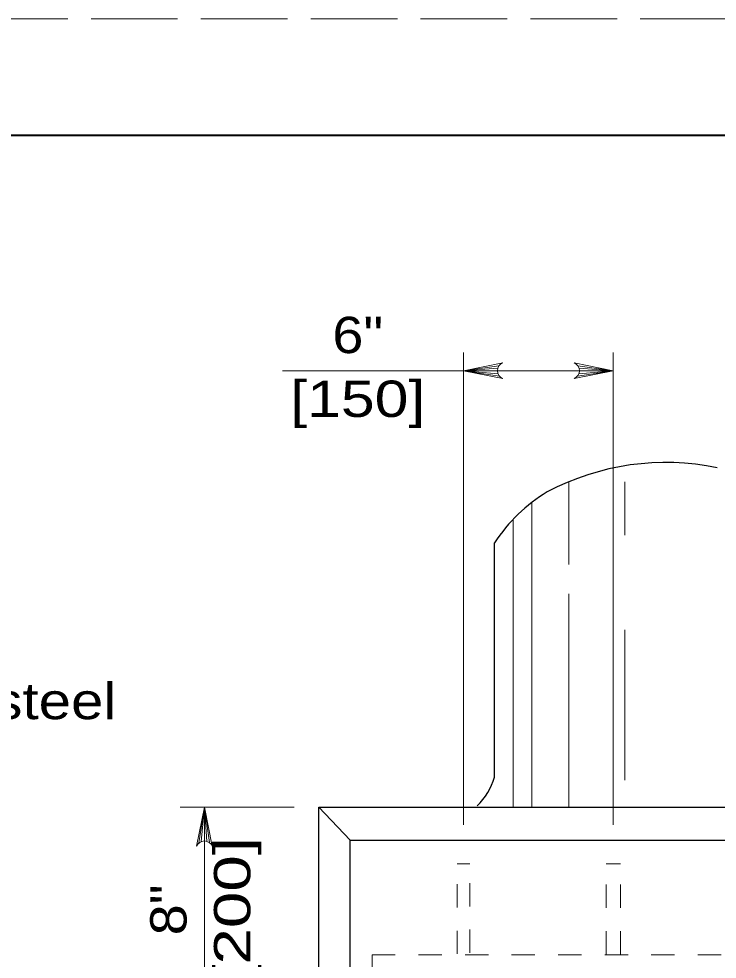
# Model space of a CAD drawing. Extents: x 1083.1 to 1117.1, y 697.4 to 719.4.
# Drawn here: x 1099.924 to 1102.925, y 715.316 to 719.354 of the extents above; entities that cross this region are included whole.
import ezdxf
from ezdxf.enums import TextEntityAlignment as Align

# ---------------------------------------------------------------- set-up
doc = ezdxf.new("R2010")
doc.units = 0
doc.header["$LTSCALE"] = 0.062
doc.linetypes.add('DOTTED', pattern=[1.5, 0.3, -1.2])
doc.linetypes.add('LONG_DASHED', pattern=[7.5, 6, -1.5])
doc.layers.add('1', color=7, linetype='Continuous', lineweight=13)

msp = doc.modelspace()

# ---------------------------------------------------------------- linework, layer by layer
at = {"layer": '1', "lineweight": 25}
for p, q in [((1085.12642, 718.85408), (1116.62642, 718.85408)), ((1101.96792, 716.09783), (1101.96792, 717.10375)), ((1101.2135, 715.96917), (1106.86575, 715.96917)), ((1101.2135, 709.98508), (1101.2135, 715.96917)), ((1101.34808, 715.82667), (1101.2135, 715.96917)), ((1101.34808, 715.82667), (1106.73117, 715.82667)), ((1101.34808, 710.1275), (1101.34808, 715.82667))]:
    msp.add_line(p, q, dxfattribs=at)
at = {"layer": '1'}
for p, q in [((1101.83475, 715.89242), (1101.83475, 717.92167)), ((1102.47817, 715.89242), (1102.47817, 717.92167)), ((1101.98708, 717.86425), (1101.83475, 717.843)), ((1101.98192, 717.85375), (1101.83475, 717.843)), ((1102.32583, 717.86425), (1102.47817, 717.843)), ((1102.331, 717.85375), (1102.47817, 717.843)), ((1101.05733, 717.843), (1102.47817, 717.843)), ((1101.98033, 717.843), (1101.83475, 717.843)), ((1101.983, 717.82933), (1101.83475, 717.843)), ((1101.98883, 717.81942), (1101.83475, 717.843)), ((1102.32408, 717.81942), (1102.47817, 717.843)), ((1102.32992, 717.82933), (1102.47817, 717.843)), ((1102.33258, 717.843), (1102.47817, 717.843)), ((1102.288, 717.01083), (1102.288, 717.36608)), ((1102.52808, 717.137), (1102.52808, 717.36608)), ((1102.12792, 715.96917), (1102.12792, 717.27708)), ((1102.04792, 715.96917), (1102.04792, 717.2045)), ((1102.288, 715.96917), (1102.288, 716.88433)), ((1102.52808, 716.08483), (1102.52808, 716.73058)), ((1100.61667, 715.96892), (1101.10775, 715.96892)), ((1100.698, 715.81483), (1100.72158, 715.96892)), ((1100.70792, 715.82067), (1100.72158, 715.96892)), ((1100.72158, 715.05042), (1100.72158, 715.96892)), ((1100.72158, 715.82333), (1100.72158, 715.96892)), ((1100.73233, 715.82175), (1100.72158, 715.96892)), ((1100.74292, 715.81658), (1100.72158, 715.96892))]:
    msp.add_line(p, q, dxfattribs=at)
at = {"layer": '1', "linetype": 'DOTTED'}
for p, q in [((1101.80767, 715.72575), (1101.86183, 715.72575)), ((1101.80767, 715.33817), (1101.80767, 715.72575)), ((1101.86183, 715.34267), (1101.86183, 715.72575)), ((1102.4475, 715.72575), (1102.50883, 715.72575)), ((1102.4475, 715.33592), (1102.4475, 715.72575)), ((1102.50883, 715.33592), (1102.50883, 715.72575)), ((1101.44158, 715.33383), (1106.624, 715.33383)), ((1101.44158, 715.26525), (1101.44158, 715.33383))]:
    msp.add_line(p, q, dxfattribs=at)
at = {"layer": '1', "linetype": 'LONG_DASHED'}
msp.add_lwpolyline([(1083.12642, 697.35408), (1117.12642, 697.35408), (1117.12642, 719.35408), (1083.12642, 719.35408)], close=True, dxfattribs=at)
at = {"layer": '1', "lineweight": 40}
msp.add_lwpolyline([(1085.12642, 718.85408), (1116.62642, 718.85408), (1116.62642, 697.85408), (1085.12642, 697.85408)], close=True, dxfattribs=at)
msp.add_lwpolyline([(1085.12642, 718.85408), (1116.62642, 718.85408), (1116.62642, 697.85408), (1085.12642, 697.85408)], close=True, dxfattribs=at)
at = {"layer": '1'}
for points in [[(1102.003, 717.80933), (1101.83475, 717.843), (1102.003, 717.87667)], [(1102.30992, 717.80933), (1102.47817, 717.843), (1102.30992, 717.87667)], [(1100.68792, 715.80067), (1100.72158, 715.96892), (1100.75525, 715.80067)]]:
    msp.add_lwpolyline(points, dxfattribs=at)
for centre, start, end in [((1102.01657, 717.84302), 112.08782, 247.91395), ((1102.29635, 717.84302), 292.08605, 67.91218), ((1100.72162, 715.7871), 22.08782, 157.91395)]:
    msp.add_arc(centre, 0.03631, start, end, dxfattribs=at)
at = {"layer": '1', "lineweight": 25}
for centre, major_axis, start_param, end_param in [((1102.70511, 716.22866), (0, 1.22024), 6.0913628, 6.7427401), ((1102.53847, 716.68284), (0, 0.7362), 0.5184487, 0.9622613), ((1101.71591, 716.18082), (0, 0.27941), 3.8810657, 4.4108036)]:
    msp.add_ellipse(centre, major_axis=major_axis, ratio=0.944544, start_param=start_param, end_param=end_param, dxfattribs=at)

# ---------------------------------------------------------------- texts
at = {"layer": '1'}
for s, width, p in [('6"', 1.15, (1101.38042, 717.91842)), ('[150]', 1.25, (1101.38042, 717.64433))]:
    msp.add_text(s, height=0.156, dxfattribs=dict(at, width=width)).set_placement(p, align=Align.CENTER)
at = {"layer": '1', "width": 1.2}
msp.add_text('Reinf. steel', height=0.156, dxfattribs=at).set_placement((1099.09075, 716.34642))
at = {"layer": '1'}
for s, width, p in [('[200]', 1.35, (1100.91858, 715.52742)), ('8"', 1.15, (1100.6445, 715.52742))]:
    msp.add_text(s, height=0.156, rotation=90, dxfattribs=dict(at, width=width)).set_placement(p, align=Align.CENTER)

doc.saveas('drawing.dxf')
